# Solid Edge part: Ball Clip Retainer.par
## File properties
Author: Dan
Template: Normal.par
Last saved by: Dan
Revision: 2
Application: Solid Edge
Density: 0 kg/mm^3
Accuracy: 0.99
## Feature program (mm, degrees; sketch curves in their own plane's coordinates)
sketch for "unnamed RevolvedProtrusion 1" plane through (0, 0, 0) normal (1, 0, 0) x-axis (0, 1, 0)
  line (0, 8) -> (0, 5.75)
  line (0, 5.75) -> (-2.5, 5.75)
  line (-2.5, 5.75) -> (-2.5, 6.55)
  line (-2.5, 6.55) -> (-1, 6.55)
  line (-1, 6.55) -> (-1, 8)
  line (-1, 8) -> (0, 8)
  dimension (linear) = 2.5
  dimension (linear) = 1
  dimension (linear) = 1
revolve "unnamed RevolvedProtrusion 1" add finite 360 deg
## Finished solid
Body 1: solid body, 6 faces, 6 edges, 0 vertices.
  Faces by surface: cylinder 3, plane 3
  Edges by curve: circle 6
Bounding box of the edges (mm): 16.000 x 2.500 x 16.000, from (-8, -2.5, -8) to (8, 0, 8).
Cylindrical faces by radius (mm): R5.75 x1, R6.55 x1, R8 x1
Planar faces by outward normal: +y 1, -y 2
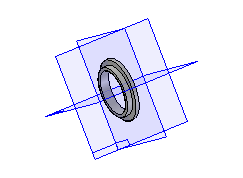
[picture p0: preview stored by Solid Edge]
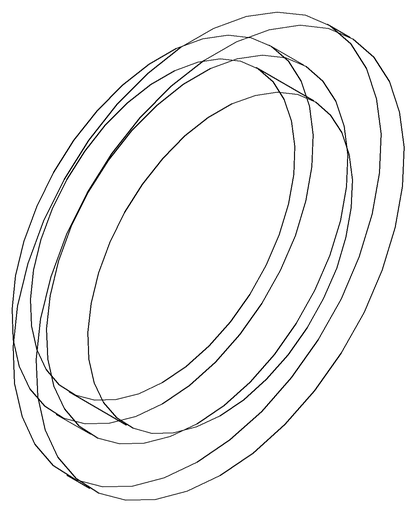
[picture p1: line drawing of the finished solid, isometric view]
